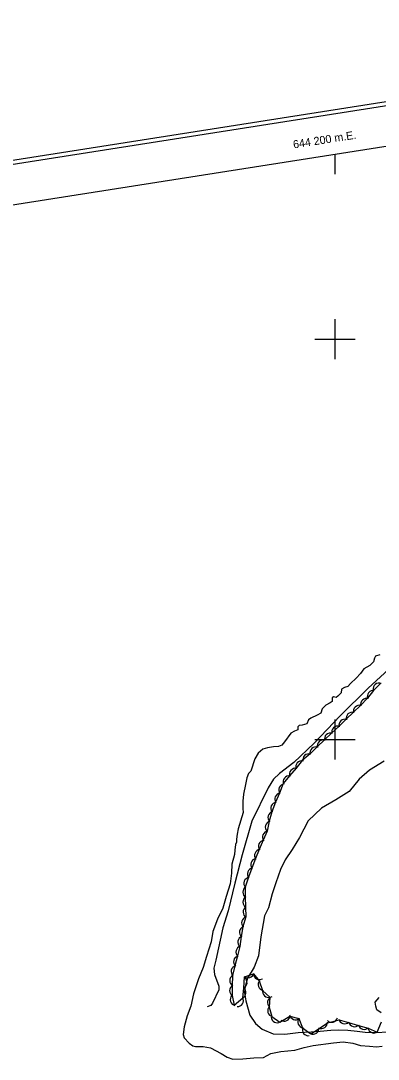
# Model space of a CAD drawing. Extents: x 643342 to 646936, y 5873857 to 5876103.
# Drawn here: x 644043 to 644222, y 5875240 to 5875759 of the extents above; entities that cross this region are included whole.
import ezdxf

# ---------------------------------------------------------------- set-up
doc = ezdxf.new("R2010")
doc.units = 0
for name, color, linetype in [('Niveau 2', 7, 'Continuous'), ('Niveau 22', 7, 'Continuous'), ('Niveau 4', 7, 'Continuous'), ('Niveau 44', 7, 'Continuous'), ('Niveau 60', 7, 'Continuous'), ('Niveau 61', 7, 'Continuous')]:
    doc.layers.add(name, color=color, linetype=linetype)

msp = doc.modelspace()

# ---------------------------------------------------------------- linework, layer by layer
at = {"layer": 'Niveau 2'}
for points in [[(644224.54, 5875389.08), (644217.18, 5875384.66), (644212.15, 5875380.1)], [(644212.15, 5875380.1), (644207.15, 5875373.88), (644200.41, 5875369.76), (644193.26, 5875365.65), (644186.6, 5875359.33), (644182.27, 5875350.98), (644178.55, 5875344.99), (644175.11, 5875339.74), (644172.76, 5875335.01), (644170.53, 5875328.27), (644168.71, 5875322.81), (644166.8, 5875315.86), (644164.74, 5875311.81), (644162.97, 5875301.3), (644161.82, 5875291.81), (644159.66, 5875286.25), (644156.26, 5875280.59), (644155.05, 5875275.66), (644154.9, 5875273.33), (644155.45, 5875269.28), (644157.54, 5875262.1), (644160.4, 5875258.09), (644163.57, 5875255.24), (644169.2, 5875252.85), (644174.91, 5875252.74), (644181.66, 5875253.55), (644188.11, 5875253.8), (644192.52, 5875254.22), (644198, 5875254.62), (644201.96, 5875254.87), (644206.49, 5875254.64), (644211.04, 5875254.18), (644215.12, 5875253.67), (644220.53, 5875253.59), (644226.43, 5875253.91)], [(644223.05, 5875263.4), (644220.91, 5875264.8), (644220.32, 5875266.7), (644220.13, 5875268.76), (644222.06, 5875271.02)]]:
    msp.add_lwpolyline(points, dxfattribs=at)
at = {"layer": 'Niveau 22'}
msp.add_lwpolyline([(644230.87, 5875438.78), (644216.55, 5875425.59), (644202.64, 5875411.72), (644189.53, 5875398.16), (644179.38, 5875388.43), (644172.27, 5875383.02), (644169.33, 5875380.13), (644166.65, 5875375.72), (644158.54, 5875359.16), (644153.67, 5875342.3), (644149.98, 5875328.16), (644146.61, 5875314.29), (644144.05, 5875305.84), (644140.54, 5875289.68), (644139.6, 5875285.67), (644139.89, 5875282.48), (644142.09, 5875276.62), (644142.02, 5875274.83), (644138.83, 5875268.1), (644138.09, 5875267.08), (644136.13, 5875266.42)], dxfattribs=at)
at = {"layer": 'Niveau 4'}
for points in [[(644222.36, 5875442.31), (644220.3, 5875441.53), (644219.79, 5875440.65), (644219.26, 5875438.7), (644217.41, 5875436.87), (644214.48, 5875435.18), (644212.67, 5875432.87), (644210.62, 5875430.67), (644207.79, 5875427.91), (644206.39, 5875426.36), (644204.76, 5875425.97), (644203.3, 5875425.12), (644203.11, 5875423.32), (644201.37, 5875421.62), (644200.6, 5875420.95), (644199.27, 5875421.19), (644198.6, 5875420.77), (644198.52, 5875418.98), (644197.63, 5875418.3), (644195.37, 5875417.15), (644193.53, 5875415.19), (644192.89, 5875413.12), (644191.08, 5875412.12), (644188.02, 5875410.53), (644186.79, 5875409.7), (644186.01, 5875407.85), (644183.59, 5875407.03), (644182.18, 5875406.9), (644181.41, 5875406.23), (644181.42, 5875404.81), (644179.81, 5875404.19), (644178.02, 5875403.07), (644174.73, 5875398.72), (644173.45, 5875397.18), (644171.85, 5875396.44), (644169.37, 5875396.33), (644166.33, 5875395.81), (644164.01, 5875395.12), (644161.58, 5875393.11), (644159.95, 5875390.23), (644158.01, 5875384.1), (644156.81, 5875382.92), (644156.07, 5875380.71), (644155.41, 5875377.44), (644154.3, 5875372.7), (644154.04, 5875369.11), (644154.01, 5875365.54), (644154.09, 5875363.41), (644151.75, 5875355.22), (644151.15, 5875352.67), (644150.79, 5875350.13), (644150.92, 5875348.72)], [(644150.92, 5875348.72), (644150.32, 5875347.47), (644149.98, 5875344.71), (644149.82, 5875342.55), (644148.48, 5875337.67), (644148.3, 5875333.13), (644147.72, 5875327.84), (644145.68, 5875321.46), (644143.96, 5875315.59), (644141.36, 5875310.23), (644139.08, 5875303.95), (644138.25, 5875298.75), (644135.82, 5875291.5), (644134.18, 5875285.99), (644131.84, 5875280.41), (644129.31, 5875272.91), (644128.09, 5875266.72), (644126.28, 5875261.79), (644124.76, 5875256.28), (644124.27, 5875252.55), (644124.67, 5875250.8), (644127.17, 5875248.17), (644129.07, 5875246.92), (644130.41, 5875246.57), (644134.22, 5875246.57), (644137.86, 5875245.84), (644143.24, 5875243.02), (644146.26, 5875241.16), (644149.08, 5875240.23), (644153.95, 5875240.34), (644159.5, 5875240.86), (644164.24, 5875241.07), (644167.99, 5875242.97), (644172.89, 5875244.03), (644179.96, 5875244.69), (644184.6, 5875245.97), (644189.14, 5875246.99), (644199.23, 5875248.42), (644204.06, 5875248.87), (644208.89, 5875248.14), (644212.79, 5875247.08), (644217.22, 5875246.66), (644220.69, 5875246.39), (644223.63, 5875246.67)]]:
    msp.add_lwpolyline(points, dxfattribs=at)
at = {"layer": 'Niveau 44'}
for points in [[(644222.9, 5875428.12), (644219.23, 5875424.48), (644216.24, 5875420.65), (644212.69, 5875416.98), (644209.21, 5875413.61), (644205.51, 5875410.03), (644202.02, 5875406.65), (644198.29, 5875403.11), (644194.77, 5875399.77), (644191.04, 5875396.22), (644187.55, 5875392.85), (644183.7, 5875389.38), (644180.57, 5875385.66), (644177.25, 5875381.73), (644174.13, 5875378.01), (644172.26, 5875373.09), (644170.32, 5875368.64), (644168.46, 5875363.81), (644167.17, 5875359.14), (644166.1, 5875354.11), (644164.2, 5875349.64), (644162.19, 5875344.91), (644160.29, 5875340.44), (644158.43, 5875335.63), (644156.75, 5875331.07), (644155.22, 5875326.11), (644155.24, 5875321.25), (644155.29, 5875316.1), (644155.44, 5875311.25), (644154.03, 5875306.34), (644153.21, 5875301.55), (644152.44, 5875296.48), (644151.27, 5875291.77), (644150.03, 5875286.78), (644148.86, 5875282.06), (644148.66, 5875276.88), (644148.62, 5875272.02), (644149.7, 5875267.1), (644154.06, 5875270.85), (644154.58, 5875275.68), (644154.76, 5875281.37), (644159.37, 5875282.89), (644162.21, 5875279.27), (644163.87, 5875274.43), (644167.41, 5875271.12), (644167.07, 5875266.26), (644168.4, 5875261.59), (644172.47, 5875258.74), (644177.54, 5875261.64), (644181.95, 5875260.44)], [(644181.95, 5875260.44), (644183.73, 5875255.93), (644188.01, 5875252.88), (644192.06, 5875255.56), (644196.23, 5875258.32), (644202.01, 5875259.87), (644206.67, 5875258.5), (644211.8, 5875257.01), (644216.48, 5875255.71), (644221.05, 5875253.72), (644223.29, 5875258.89)]]:
    msp.add_lwpolyline(points, dxfattribs=at)
for centre, start, end in [((644221.97, 5875425.14), 68.3536, 188.3315), ((644221.97, 5875425.14), 68.3536, 188.3315), ((644221.97, 5875425.14), 68.3536, 188.3315), ((644219.12, 5875421.48), 81.9756, 201.9536), ((644219.12, 5875421.48), 81.9756, 201.9536), ((644219.12, 5875421.48), 81.9756, 201.9536), ((644215.77, 5875417.5), 74.0819, 194.0599), ((644215.77, 5875417.5), 74.0819, 194.0599), ((644215.77, 5875417.5), 74.0819, 194.0599), ((644208.58, 5875410.55), 74.0819, 194.0599), ((644208.58, 5875410.55), 74.0819, 194.0599), ((644208.58, 5875410.55), 74.0819, 194.0599), ((644212.18, 5875414.03), 74.0819, 194.0599), ((644212.18, 5875414.03), 74.0819, 194.0599), ((644212.18, 5875414.03), 74.0819, 194.0599), ((644204.99, 5875407.07), 74.0819, 194.0599), ((644204.99, 5875407.07), 74.0819, 194.0599), ((644204.99, 5875407.07), 74.0819, 194.0599), ((644197.74, 5875400.16), 73.5189, 193.4968), ((644197.74, 5875400.16), 73.5189, 193.4968), ((644197.74, 5875400.16), 73.5189, 193.4968), ((644201.37, 5875403.61), 73.5189, 193.4968), ((644201.37, 5875403.61), 73.5189, 193.4968), ((644201.37, 5875403.61), 73.5189, 193.4968), ((644194.11, 5875396.72), 73.5189, 193.4968), ((644194.11, 5875396.72), 73.5189, 193.4968), ((644194.11, 5875396.72), 73.5189, 193.4968), ((644186.93, 5875389.79), 74.0486, 194.0266), ((644186.93, 5875389.79), 74.0486, 194.0266), ((644186.93, 5875389.79), 74.0486, 194.0266), ((644190.52, 5875393.27), 74.0486, 194.0266), ((644190.52, 5875393.27), 74.0486, 194.0266), ((644190.52, 5875393.27), 74.0486, 194.0266), ((644183.48, 5875386.38), 79.9091, 199.8871), ((644183.48, 5875386.38), 79.9091, 199.8871), ((644183.48, 5875386.38), 79.9091, 199.8871), ((644177.04, 5875378.74), 79.9091, 199.8871), ((644177.04, 5875378.74), 79.9091, 199.8871), ((644177.04, 5875378.74), 79.9091, 199.8871), ((644180.26, 5875382.56), 79.9091, 199.8871), ((644180.26, 5875382.56), 79.9091, 199.8871), ((644180.26, 5875382.56), 79.9091, 199.8871), ((644174.9, 5875374.74), 96.4173, 216.3952), ((644174.9, 5875374.74), 96.4173, 216.3952), ((644174.9, 5875374.74), 96.4173, 216.3952), ((644172.9, 5875370.16), 96.4173, 216.3952), ((644172.9, 5875370.16), 96.4173, 216.3952), ((644172.9, 5875370.16), 96.4173, 216.3952), ((644170.9, 5875365.58), 96.4173, 216.3952), ((644170.9, 5875365.58), 96.4173, 216.3952), ((644170.9, 5875365.58), 96.4173, 216.3952), ((644169.52, 5875361.01), 104.5557, 224.5336), ((644169.52, 5875361.01), 104.5557, 224.5336), ((644169.52, 5875361.01), 104.5557, 224.5336), ((644168.18, 5875356.19), 104.5557, 224.5336), ((644168.18, 5875356.19), 104.5557, 224.5336), ((644168.18, 5875356.19), 104.5557, 224.5336), ((644166.78, 5875351.18), 96.9556, 216.9336), ((644166.78, 5875351.18), 96.9556, 216.9336), ((644166.78, 5875351.18), 96.9556, 216.9336), ((644162.86, 5875341.98), 96.9556, 216.9336), ((644162.86, 5875341.98), 96.9556, 216.9336), ((644162.86, 5875341.98), 96.9556, 216.9336), ((644164.82, 5875346.58), 96.9556, 216.9336), ((644164.82, 5875346.58), 96.9556, 216.9336), ((644164.82, 5875346.58), 96.9556, 216.9336), ((644160.98, 5875337.42), 99.6459, 219.6239), ((644160.98, 5875337.42), 99.6459, 219.6239), ((644160.98, 5875337.42), 99.6459, 219.6239), ((644159.24, 5875332.74), 99.6459, 219.6239), ((644159.24, 5875332.74), 99.6459, 219.6239), ((644159.24, 5875332.74), 99.6459, 219.6239), ((644157.5, 5875328.05), 99.6459, 219.6239), ((644157.5, 5875328.05), 99.6459, 219.6239), ((644157.5, 5875328.05), 99.6459, 219.6239), ((644156.99, 5875323.69), 120.2632, 240.2412), ((644156.99, 5875323.69), 120.2632, 240.2412), ((644156.99, 5875323.69), 120.2632, 240.2412), ((644157.01, 5875318.69), 120.2632, 240.2412), ((644157.01, 5875318.69), 120.2632, 240.2412), ((644157.01, 5875318.69), 120.2632, 240.2412), ((644157.13, 5875313.73), 121.7595, 241.7374), ((644157.13, 5875313.73), 121.7595, 241.7374), ((644157.13, 5875313.73), 121.7595, 241.7374), ((644156.4, 5875308.4), 105.297, 225.275), ((644156.4, 5875308.4), 105.297, 225.275), ((644156.4, 5875308.4), 105.297, 225.275), ((644155.36, 5875303.65), 110.2277, 230.2056), ((644155.36, 5875303.65), 110.2277, 230.2056), ((644155.36, 5875303.65), 110.2277, 230.2056), ((644154.51, 5875298.72), 110.2277, 230.2056), ((644154.51, 5875298.72), 110.2277, 230.2056), ((644154.51, 5875298.72), 110.2277, 230.2056), ((644153.57, 5875293.7), 106.0812, 226.0592), ((644153.57, 5875293.7), 106.0812, 226.0592), ((644153.57, 5875293.7), 106.0812, 226.0592), ((644152.36, 5875288.85), 106.0812, 226.0592), ((644152.36, 5875288.85), 106.0812, 226.0592), ((644152.36, 5875288.85), 106.0812, 226.0592), ((644151.16, 5875284), 106.0812, 226.0592), ((644151.16, 5875284), 106.0812, 226.0592), ((644151.16, 5875284), 106.0812, 226.0592), ((644156.52, 5875283.81), 228.187, 348.1649), ((644156.52, 5875283.81), 228.187, 348.1649), ((644156.52, 5875283.81), 228.187, 348.1649), ((644162.25, 5875282.98), 181.0412, 301.0191), ((644162.25, 5875282.98), 181.0412, 301.0191), ((644162.25, 5875282.98), 181.0412, 301.0191), ((644150.45, 5875279.43), 119.4883, 239.4663), ((644150.45, 5875279.43), 119.4883, 239.4663), ((644150.45, 5875279.43), 119.4883, 239.4663), ((644153.11, 5875278.42), 293.8118, 53.7897), ((644153.11, 5875278.42), 293.8118, 53.7897), ((644153.11, 5875278.42), 293.8118, 53.7897), ((644164.63, 5875277.49), 137.6862, 257.6642), ((644164.63, 5875277.49), 137.6862, 257.6642), ((644164.63, 5875277.49), 137.6862, 257.6642), ((644150.4, 5875274.43), 119.4883, 239.4663), ((644150.4, 5875274.43), 119.4883, 239.4663), ((644150.4, 5875274.43), 119.4883, 239.4663), ((644152.56, 5875273.45), 293.8118, 53.7897), ((644152.56, 5875273.45), 293.8118, 53.7897), ((644152.56, 5875273.45), 293.8118, 53.7897), ((644166.84, 5875274.06), 166.9324, 286.9103), ((644166.84, 5875274.06), 166.9324, 286.9103), ((644166.84, 5875274.06), 166.9324, 286.9103), ((644150.7, 5875269.93), 136.5681, 256.546), ((644150.7, 5875269.93), 136.5681, 256.546), ((644150.7, 5875269.93), 136.5681, 256.546), ((644151.29, 5875269.44), 268.0879, 28.0658), ((644151.29, 5875269.44), 268.0879, 28.0658), ((644151.29, 5875269.44), 268.0879, 28.0658), ((644169.32, 5875268.51), 107.4093, 227.3873), ((644169.32, 5875268.51), 107.4093, 227.3873), ((644169.32, 5875268.51), 107.4093, 227.3873), ((644169.43, 5875264.4), 135.8797, 255.8576), ((644169.43, 5875264.4), 135.8797, 255.8576), ((644169.43, 5875264.4), 135.8797, 255.8576), ((644174.58, 5875262.14), 236.4322, 356.4101), ((644174.58, 5875262.14), 236.4322, 356.4101), ((644174.58, 5875262.14), 236.4322, 356.4101), ((644180.34, 5875262.87), 188.7859, 308.7639), ((644180.34, 5875262.87), 188.7859, 308.7639), ((644180.34, 5875262.87), 188.7859, 308.7639), ((644171.09, 5875261.4), 183.3349, 303.3128), ((644171.09, 5875261.4), 183.3349, 303.3128), ((644171.09, 5875261.4), 183.3349, 303.3128), ((644184.48, 5875258.83), 141.5769, 261.5548), ((644184.48, 5875258.83), 141.5769, 261.5548), ((644184.48, 5875258.83), 141.5769, 261.5548), ((644193.23, 5875258.45), 243.4707, 3.4487), ((644193.23, 5875258.45), 243.4707, 3.4487), ((644193.23, 5875258.45), 243.4707, 3.4487), ((644198.32, 5875261.66), 224.7297, 344.7077), ((644198.32, 5875261.66), 224.7297, 344.7077), ((644198.32, 5875261.66), 224.7297, 344.7077), ((644204.84, 5875260.87), 193.5744, 313.5523), ((644204.84, 5875260.87), 193.5744, 313.5523), ((644204.84, 5875260.87), 193.5744, 313.5523), ((644209.8, 5875259.4), 194.4363, 314.4142), ((644209.8, 5875259.4), 194.4363, 314.4142), ((644209.8, 5875259.4), 194.4363, 314.4142), ((644214.61, 5875258.06), 194.4363, 314.4142), ((644214.61, 5875258.06), 194.4363, 314.4142), ((644214.61, 5875258.06), 194.4363, 314.4142), ((644186.7, 5875254.91), 158.3937, 278.3716), ((644186.7, 5875254.91), 158.3937, 278.3716), ((644186.7, 5875254.91), 158.3937, 278.3716), ((644189.06, 5875255.69), 243.4707, 3.4487), ((644189.06, 5875255.69), 243.4707, 3.4487), ((644189.06, 5875255.69), 243.4707, 3.4487), ((644219.43, 5875256.24), 188.7823, 308.7602), ((644219.43, 5875256.24), 188.7823, 308.7602), ((644219.43, 5875256.24), 188.7823, 308.7602)]:
    msp.add_arc(centre, 3, start, end, dxfattribs=at)
at = {"layer": 'Niveau 60'}
msp.add_line((644200, 5875692.53), (644200, 5875682.53), dxfattribs=at)
for points in [[(643342.09, 5875579.85), (646664.86, 5876102.57), (646935.9, 5874379.74), (643613.15, 5873856.99), (643342.1, 5875579.83)], [(643342.09, 5875579.85), (646664.86, 5876102.57), (646935.9, 5874379.74), (643613.15, 5873856.99), (643342.1, 5875579.83)], [(643342.09, 5875579.85), (646664.86, 5876102.57), (646935.9, 5874379.74), (643613.15, 5873856.99), (643342.1, 5875579.83)], [(643344.38, 5875578.18), (646663.19, 5876100.29), (646933.6, 5874381.38), (643614.81, 5873859.28), (643344.38, 5875578.18)], [(643344.38, 5875578.18), (646663.19, 5876100.29), (646933.6, 5874381.38), (643614.81, 5873859.28), (643344.38, 5875578.18)], [(643344.38, 5875578.18), (646663.19, 5876100.29), (646933.6, 5874381.38), (643614.81, 5873859.28), (643344.38, 5875578.18)]]:
    msp.add_lwpolyline(points, dxfattribs=at)
msp.add_lwpolyline([(643367.26, 5875561.52), (646133.22, 5875996.67), (646397.42, 5874317.29), (643631.46, 5873882.15)], close=True, dxfattribs=at)
at = {"layer": 'Niveau 61'}
for points in [[(644200, 5875610), (644200, 5875600), (644200, 5875590)], [(644190, 5875600), (644200, 5875600), (644210, 5875600)], [(644200, 5875410), (644200, 5875400), (644200, 5875390)], [(644190, 5875400), (644200, 5875400), (644210, 5875400)]]:
    msp.add_lwpolyline(points, dxfattribs=at)

# ---------------------------------------------------------------- texts
msp.add_text('644 200 m.E.', height=3.9998, rotation=8.9407, dxfattribs=at).set_placement((644179.4, 5875695.3))

doc.saveas('drawing.dxf')
